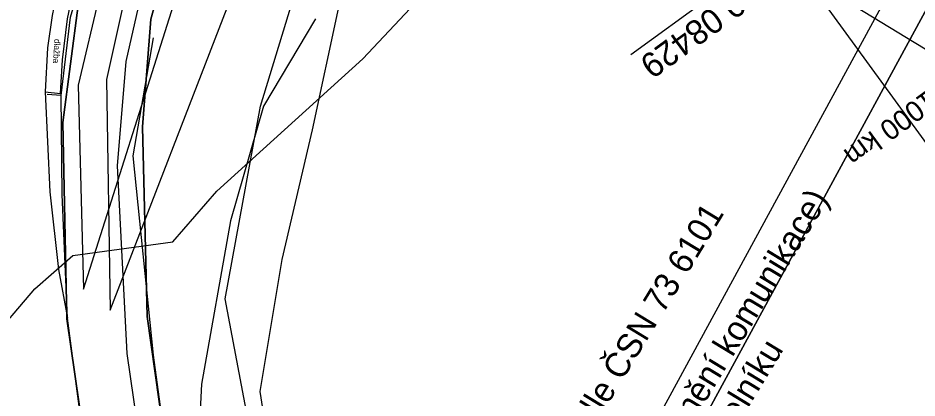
# Model space of a CAD drawing. Extents: x -555887 to -552101, y -1100251 to -1096546.
# Drawn here: x -554080.2 to -553970.5, y -1097444.9 to -1097398.4 of the extents above; entities that cross this region are included whole.
import ezdxf

# ---------------------------------------------------------------- set-up
doc = ezdxf.new("R2010")
doc.units = 0
for name, color, linetype in [('PARCELY_silnice', 7, 'Continuous'), ('PARCELY_VHO', 7, 'Continuous'), ('POLYGONY_SITUACE_PF_POPISY', 7, 'Continuous'), ('ROZHLED_ram_legenda_1', 7, 'Continuous'), ('ROZHLED_ram_legenda_2', 7, 'Continuous'), ('ROZHLED_trojuhelniky_1', 7, 'Continuous'), ('ROZHLED_trojuhelniky_2', 7, 'Continuous'), ('vrstevnice', 7, 'Continuous'), ('ZSST', 7, 'Continuous'), ('zájem', 7, 'Continuous')]:
    doc.layers.add(name, color=color, linetype=linetype)

msp = doc.modelspace()

# ---------------------------------------------------------------- linework, layer by layer
msp.add_line((-553988.41, -1097390.52), (-554005.44, -1097402.96))
at = {"layer": 'PARCELY_silnice'}
msp.add_lwpolyline([(-554030.91, -1097678.33), (-554047.02, -1097559.88), (-554049.28, -1097545.25), (-554058.01, -1097480.43), (-554064.42, -1097434.91), (-554064.99, -1097411.72), (-554063.97, -1097398.61), (-554060.96, -1097387.79), (-554052.99, -1097367.96), (-554038.93, -1097345.45), (-554044.87, -1097337.64), (-554059.66, -1097363.67), (-554062.54, -1097368.79), (-554069.61, -1097384.37), (-554072.86, -1097396.87), (-554074.7, -1097411.2), (-554074.25, -1097435.16), (-554067.74, -1097480.24), (-554068.8, -1097484.92), (-554059.78, -1097555.8), (-554058.52, -1097564.24), (-554053.21, -1097604.42), (-554046.53, -1097659.36)], dxfattribs=at)
at = {"layer": 'PARCELY_VHO'}
for points in [[(-553890.36, -1097670.23), (-553902.88, -1097642.35), (-553905.32, -1097611.67), (-553898.3, -1097524.98), (-553901.53, -1097506.94), (-553991.85, -1097382.83), (-554027.72, -1097360.75), (-554038.93, -1097345.45), (-554044.87, -1097337.64), (-554055.91, -1097333.12), (-554068.1, -1097310.12), (-554076.3, -1097297.37), (-554083.64, -1097283.44), (-554094.93, -1097256.14), (-554100.02, -1097244.94), (-554114.01, -1097204.34), (-554130.46, -1097180.06), (-554159.17, -1097101.34)], [(-553913.5, -1097649.75), (-553920.52, -1097625.16), (-553955.15, -1097551.67), (-553965.19, -1097535.15), (-553992.85, -1097506.35), (-554009.99, -1097493.12), (-554030.15, -1097490.89), (-554047.7, -1097471.03), (-554054.93, -1097432.75), (-554050.62, -1097409.22), (-554043.26, -1097385.04), (-554052.99, -1097367.96), (-554060.96, -1097387.79), (-554063.97, -1097398.61), (-554064.99, -1097411.72), (-554064.42, -1097434.91), (-554058.01, -1097480.43), (-554033.54, -1097499.24), (-554014.25, -1097501.88), (-553995.42, -1097511.01), (-553971.19, -1097536.91), (-553964.25, -1097552.71), (-553927.41, -1097628.08), (-553920.29, -1097651.1)]]:
    msp.add_lwpolyline(points, dxfattribs=at)
at = {"layer": 'ROZHLED_ram_legenda_1'}
msp.add_lwpolyline([(-554022.39, -1097495.03), (-554206.96, -1097394.87), (-554065.3, -1097133.83), (-553880.73, -1097233.99)], close=True, dxfattribs=at)
msp.add_lwpolyline([(-554022.39, -1097495.03), (-554206.96, -1097394.87), (-554065.3, -1097133.83), (-553880.73, -1097233.99)], close=True, dxfattribs=at)
for points in [[(-553880.73, -1097233.99), (-554065.3, -1097133.83), (-554206.96, -1097394.87), (-554022.39, -1097495.03), (-553880.73, -1097233.99)], [(-554200.18, -1097392.86), (-554063.29, -1097140.61), (-553887.51, -1097236), (-554024.4, -1097488.25), (-554200.18, -1097392.86)], [(-554200.18, -1097392.86), (-554063.29, -1097140.61), (-553887.51, -1097236), (-554024.4, -1097488.25), (-554200.18, -1097392.86)]]:
    msp.add_lwpolyline(points, dxfattribs=at)
at = {"layer": 'ROZHLED_ram_legenda_2'}
msp.add_lwpolyline([(-553978.03, -1097397.09), (-553881.36, -1097238.19), (-553824.97, -1097272.49), (-553921.64, -1097431.39)], close=True, dxfattribs=at)
at = {"layer": 'ROZHLED_trojuhelniky_1'}
msp.add_line((-554072.18, -1097431.54), (-554036.49, -1097318.43), dxfattribs=at)
msp.add_lwpolyline([(-554032.68, -1097321.2), (-554060.95, -1097370.23), (-554067.57, -1097384.31), (-554072.85, -1097406.64), (-554072.18, -1097431.54)], dxfattribs=at)
at = {"layer": 'ROZHLED_trojuhelniky_2'}
msp.add_line((-554068.93, -1097434.12), (-554027.51, -1097326.85), dxfattribs=at)
msp.add_lwpolyline([(-554030.47, -1097323.45), (-554058.75, -1097371.31), (-554064.7, -1097384.89), (-554069.39, -1097405.96), (-554068.93, -1097434.12)], dxfattribs=at)
at = {"layer": 'vrstevnice'}
msp.add_lwpolyline([(-554190.33, -1097523.08), (-554168.99, -1097521.25), (-554160, -1097519.71), (-554148.91, -1097516.2), (-554142.87, -1097513.11), (-554135.29, -1097507.77), (-554123.07, -1097495.14), (-554117.17, -1097487.41), (-554094.99, -1097453.71), (-554083.89, -1097438.27), (-554078.14, -1097431.53), (-554073.5, -1097427.46), (-554061.29, -1097425.77), (-554055.95, -1097419.59), (-554038.12, -1097403.45), (-554032.36, -1097397.27), (-554025.34, -1097386.03), (-554021.07, -1097375.17)], dxfattribs=at)
at = {"layer": 'ZSST'}
for p, q in [((-554074.94, -1097407.92), (-554076.63, -1097407.78)), ((-554074.15, -1097435.11), (-554074.79, -1097419.98)), ((-554070.38, -1097463.67), (-554074.15, -1097435.11))]:
    msp.add_line(p, q, dxfattribs=at)
for points in [[(-554052.25, -1097540.48), (-554066.88, -1097439.41), (-554068.04, -1097416.49), (-554067.01, -1097403.76), (-554063.04, -1097386.34), (-554059.5, -1097377.06)], [(-554071.53, -1097390.75), (-554071.75, -1097389.79), (-554072.54, -1097389.39), (-554074.08, -1097389.71), (-554074.78, -1097392.24), (-554076.03, -1097398.13), (-554076.57, -1097402.1), (-554076.89, -1097407.48), (-554076.29, -1097419.66), (-554075.23, -1097429.16), (-554074.15, -1097435.11)], [(-554074.79, -1097419.98), (-554074.94, -1097407.92), (-554073.79, -1097398.34), (-554071.53, -1097390.75)], [(-554074.14, -1097398.57), (-554072.93, -1097392.69), (-554074.78, -1097392.24)], [(-554041.11, -1097397.12), (-554044.32, -1097412.11), (-554048.01, -1097427.93), (-554050.67, -1097444.04), (-554048.27, -1097459.6), (-554042, -1097470.14), (-554037.74, -1097478.62), (-554033.95, -1097486.93), (-554027.65, -1097493.26), (-554019.52, -1097492), (-554008.89, -1097493.27), (-554003.64, -1097496.63), (-553994.28, -1097505.16), (-553985.02, -1097510.4), (-553975.58, -1097519.29), (-553972.07, -1097524.68), (-553966.56, -1097533.56), (-553961.13, -1097544.92), (-553948.08, -1097565.91), (-553939.6, -1097584.69), (-553931.83, -1097597.83), (-553917.93, -1097595.69)], [(-554076.89, -1097407.48), (-554075.02, -1097407.65), (-554074.77, -1097403.55), (-554074.14, -1097398.57)], [(-554043.9, -1097398.55), (-554050.26, -1097409.22), (-554054.28, -1097423.2), (-554057.8, -1097443.14), (-554058.38, -1097454.4), (-554057.18, -1097461.11), (-554052.44, -1097467.81), (-554037.74, -1097478.62), (-554035.3, -1097487.51), (-554032.42, -1097491.85), (-554028.44, -1097494.72), (-554019.58, -1097493.05), (-554009.9, -1097494.22), (-553995.49, -1097505.84), (-553986.52, -1097514.94), (-553975.58, -1097519.29)], [(-554063.7, -1097400.87), (-554066.17, -1097415.29), (-554063.7, -1097439.6), (-554055.31, -1097501.24)]]:
    msp.add_lwpolyline(points, dxfattribs=at)
at = {"layer": 'zájem'}
for points in [[(-554209.05, -1097338.04), (-554121.59, -1097427.95), (-554119.85, -1097429.74), (-554117.62, -1097427.68), (-554074.61, -1097473), (-554067.74, -1097480.24), (-554074.25, -1097435.16), (-554074.7, -1097411.2), (-554072.86, -1097396.87), (-554069.61, -1097384.37), (-554062.54, -1097368.79), (-554059.66, -1097363.67), (-554044.87, -1097337.64), (-554055.91, -1097333.12), (-554068.1, -1097310.12), (-554076.3, -1097297.37), (-554083.64, -1097283.44), (-554094.93, -1097256.14), (-554100.02, -1097244.94), (-554114.01, -1097204.34), (-554130.46, -1097180.06), (-554159.17, -1097101.34)], [(-554159.17, -1097101.34), (-554130.46, -1097180.06), (-554114.01, -1097204.34), (-554100.02, -1097244.94), (-554094.93, -1097256.14), (-554083.64, -1097283.44), (-554076.3, -1097297.37), (-554068.1, -1097310.12), (-554055.91, -1097333.12), (-554044.87, -1097337.64), (-554059.66, -1097363.67), (-554062.54, -1097368.79), (-554069.61, -1097384.37), (-554072.86, -1097396.87), (-554074.7, -1097411.2), (-554074.25, -1097435.16), (-554067.74, -1097480.24), (-554074.61, -1097473), (-554117.62, -1097427.68), (-554119.85, -1097429.74), (-554121.59, -1097427.95), (-554209.05, -1097338.04)]]:
    msp.add_lwpolyline(points, dxfattribs=at)

# ---------------------------------------------------------------- texts
msp.add_text('KT 0.08429', height=3, rotation=216.128).set_placement((-553987.82, -1097391.33))
at = {"layer": 'POLYGONY_SITUACE_PF_POPISY'}
msp.add_text('0.11000 km', height=2.5, rotation=216.128, dxfattribs=at).set_placement((-553965.56, -1097404.44))
at = {"layer": 'ROZHLED_ram_legenda_2'}
for s, height, rotation, p in [('Rozhledové poměry - napojení DC4 na  silnici II/446', 4, 58.6856, (-554131.93, -1097414.48)), ('l=3m (od hrany zpevnění komunikace)', 3, 58.6855, (-554016.63, -1097478.72)), ('Určení rozhledu dle ČSN 73 6101', 3, 58.6855, (-554025.17, -1097473.52)), ('Z rozhledového trojúhelníku', 3, 58.6855, (-554012.47, -1097481.18))]:
    msp.add_text(s, height=height, rotation=rotation, dxfattribs=at).set_placement(p)
at = {"layer": 'ZSST'}
msp.add_text('dlažba', height=0.75, rotation=266.7119, dxfattribs=at).set_placement((-554075.74, -1097401))

doc.saveas('drawing.dxf')
